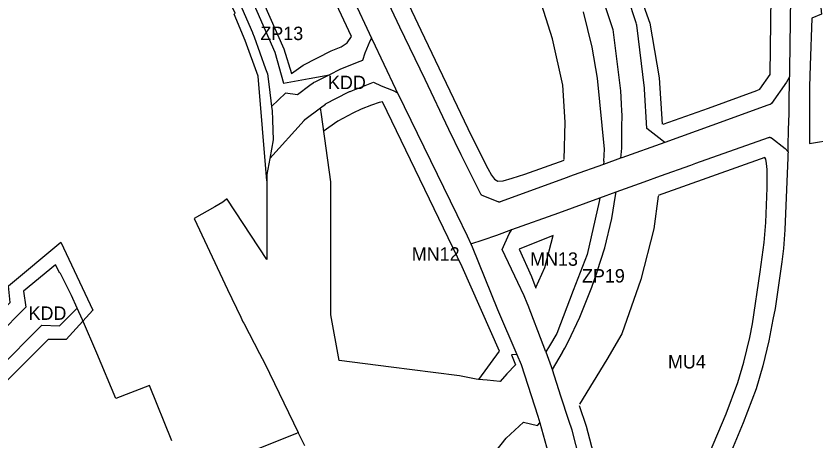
# Model space of a CAD drawing. Extents: x 7428103 to 7431580, y 5545880 to 5549002.
# Drawn here: x 7429886.6 to 7430217.3, y 5547654.9 to 5547830.4 of the extents above; entities that cross this region are included whole.
import ezdxf

# ---------------------------------------------------------------- set-up
doc = ezdxf.new("R2010")
doc.units = 0
for name, color, linetype in [('CZ_L_linie rozgraniczające tereny o różnym przeznaczeniu oraz różnych warunkach ich zabudowy i zagospodarowania', 7, 'Continuous'), ('CZ_L_maksymalne nieprzekraczalne linie zabudowy', 7, 'Continuous'), ('CZ_L_opisy_linie rozgraniczające tereny o różnym przeznaczeniu oraz różnych warunkach ich zabudowy i zagospodarowania', 7, 'Continuous'), ('Łąki_Nowohuckie', 7, 'Continuous')]:
    doc.layers.add(name, color=color, linetype=linetype)

msp = doc.modelspace()

# ---------------------------------------------------------------- linework, layer by layer
at = {"layer": 'CZ_L_linie rozgraniczające tereny o różnym przeznaczeniu oraz różnych warunkach ich zabudowy i zagospodarowania'}
for p, q in [((7430045.43, 5547825.76), (7430030.02, 5547858.79)), ((7430017.37, 5547856.33), (7430033.75, 5547821.24)), ((7429971.54, 5547853.7), (7429984.45, 5547823.58)), ((7429979.57, 5547847.56), (7429993.81, 5547815.38)), ((7430143.29, 5547827.5), (7430136.95, 5547846.57)), ((7430207.23, 5547844.23), (7430206.76, 5547808.41)), ((7430127.52, 5547843.26), (7430133.64, 5547824.82)), ((7430121.33, 5547832.07), (7430124.89, 5547817.41)), ((7430143.39, 5547826.93), (7430143.29, 5547827.5)), ((7430045.44, 5547825.74), (7430045.43, 5547825.76)), ((7430055.96, 5547804.15), (7430045.44, 5547825.74)), ((7430133.64, 5547824.82), (7430136.74, 5547799.38)), ((7430143.51, 5547826.52), (7430143.39, 5547826.93)), ((7430146.68, 5547800.44), (7430143.51, 5547826.52)), ((7429984.45, 5547823.58), (7429984.52, 5547823.42)), ((7429984.52, 5547823.42), (7429985.24, 5547821.72)), ((7429985.24, 5547821.72), (7429989.93, 5547808.56)), ((7430033.75, 5547821.24), (7430032.99, 5547819.91)), ((7430034.12, 5547820.45), (7430033.75, 5547821.24)), ((7430032.99, 5547819.91), (7430031, 5547814.97)), ((7430043.84, 5547800.03), (7430034.12, 5547820.45)), ((7430124.89, 5547817.41), (7430127.16, 5547804.59)), ((7429993.81, 5547815.38), (7429997.37, 5547802.59)), ((7430031, 5547814.97), (7430030, 5547811.9)), ((7430027.84, 5547811.07), (7430020.59, 5547808.23)), ((7430030, 5547811.9), (7430027.84, 5547811.07)), ((7429989.93, 5547808.56), (7429990.71, 5547806.38)), ((7430020.59, 5547808.23), (7430016.36, 5547806.08)), ((7430206.76, 5547808.41), (7430206.74, 5547807.07)), ((7429990.71, 5547806.38), (7429991.36, 5547801.02)), ((7429997.37, 5547802.59), (7430008.01, 5547804.54)), ((7430008.01, 5547804.54), (7430016.36, 5547806.08)), ((7430016.36, 5547806.08), (7430010.53, 5547803.12)), ((7430065.78, 5547783.47), (7430055.96, 5547804.15)), ((7430127.16, 5547804.59), (7430129.96, 5547775.23)), ((7430206.72, 5547805.14), (7430205.44, 5547803.05)), ((7430206.67, 5547801.74), (7430206.72, 5547805.14)), ((7430206.74, 5547807.07), (7430206.72, 5547805.14)), ((7429991.36, 5547801.02), (7429992.37, 5547792.88)), ((7430008.26, 5547801.65), (7430003.16, 5547797.78)), ((7430009.65, 5547802.64), (7430008.26, 5547801.65)), ((7430009.68, 5547802.67), (7430009.65, 5547802.64)), ((7430009.65, 5547802.64), (7430009.65, 5547802.64)), ((7430010.53, 5547803.12), (7430009.68, 5547802.67)), ((7430027.63, 5547800.27), (7430034.64, 5547802.98)), ((7430034.64, 5547802.98), (7430037.8, 5547801.52)), ((7430037.8, 5547801.52), (7430042.71, 5547799.49)), ((7430205.44, 5547803.05), (7430199.23, 5547794.21)), ((7430206.61, 5547797.26), (7430206.67, 5547801.26)), ((7430206.67, 5547801.26), (7430206.67, 5547801.74)), ((7429998.18, 5547798.5), (7429992.37, 5547792.88)), ((7430003.16, 5547797.77), (7429998.18, 5547798.5)), ((7430003.16, 5547797.78), (7430003.16, 5547797.77)), ((7430018.96, 5547796.18), (7430024.67, 5547799.09)), ((7430024.67, 5547799.09), (7430024.76, 5547799.13)), ((7430024.76, 5547799.13), (7430024.89, 5547799.18)), ((7430024.89, 5547799.18), (7430027.61, 5547800.26)), ((7430027.61, 5547800.26), (7430027.63, 5547800.27)), ((7430042.71, 5547799.49), (7430044.51, 5547798.64)), ((7430044.51, 5547798.64), (7430043.84, 5547800.03)), ((7430044.51, 5547798.64), (7430069.01, 5547748.21)), ((7430136.74, 5547799.38), (7430137.07, 5547793.99)), ((7430146.71, 5547800.16), (7430146.68, 5547800.44)), ((7430146.71, 5547800.14), (7430146.71, 5547800.16)), ((7430147.72, 5547783.75), (7430146.71, 5547800.14)), ((7430015.04, 5547794.19), (7430018.96, 5547796.18)), ((7430199.23, 5547794.21), (7430199.18, 5547794.15)), ((7430206.52, 5547790.05), (7430206.6, 5547796.02)), ((7430206.6, 5547796.02), (7430206.61, 5547797.26)), ((7429992.37, 5547792.88), (7429992.58, 5547791.1)), ((7429992.58, 5547791.1), (7429992.73, 5547787.51)), ((7430006.19, 5547787.52), (7430012.59, 5547792.38)), ((7430012.59, 5547792.38), (7430014.66, 5547793.95)), ((7430013.01, 5547789.56), (7430012.59, 5547792.38)), ((7430014.66, 5547793.95), (7430014.7, 5547793.98)), ((7430014.7, 5547793.98), (7430014.83, 5547794.07)), ((7430014.83, 5547794.07), (7430014.97, 5547794.15)), ((7430014.97, 5547794.15), (7430015.04, 5547794.19)), ((7430137.07, 5547793.99), (7430137.26, 5547791)), ((7430137.26, 5547791), (7430137.35, 5547789.46)), ((7430197.69, 5547793.42), (7430174.6, 5547785.04)), ((7430198.63, 5547793.76), (7430197.69, 5547793.42)), ((7430198.66, 5547793.77), (7430198.63, 5547793.76)), ((7430198.73, 5547793.8), (7430198.66, 5547793.77)), ((7430198.8, 5547793.84), (7430198.73, 5547793.8)), ((7430198.88, 5547793.88), (7430198.8, 5547793.84)), ((7430198.94, 5547793.92), (7430198.88, 5547793.88)), ((7430199.01, 5547793.97), (7430198.94, 5547793.92)), ((7430199.03, 5547794), (7430199.01, 5547793.97)), ((7430199.07, 5547794.03), (7430199.03, 5547794)), ((7430199.13, 5547794.09), (7430199.07, 5547794.03)), ((7430199.18, 5547794.15), (7430199.13, 5547794.09)), ((7430016.91, 5547761.69), (7430013.01, 5547789.56)), ((7430137.35, 5547789.46), (7430137.25, 5547784.18)), ((7430206.34, 5547783.33), (7430206.52, 5547790.05)), ((7429992.73, 5547787.51), (7429992.74, 5547787.33)), ((7429992.74, 5547787.33), (7429993.08, 5547779.09)), ((7430002.01, 5547782.9), (7430005.84, 5547787.19)), ((7430005.84, 5547787.19), (7430005.87, 5547787.22)), ((7430005.87, 5547787.22), (7430005.98, 5547787.34)), ((7430005.98, 5547787.34), (7430006.11, 5547787.45)), ((7430006.11, 5547787.45), (7430006.19, 5547787.52)), ((7430174.59, 5547785.04), (7430155.16, 5547778.08)), ((7430174.6, 5547785.04), (7430174.59, 5547785.04)), ((7429995.56, 5547775.68), (7430002.01, 5547782.9)), ((7430065.78, 5547783.46), (7430065.78, 5547783.47)), ((7430070.89, 5547772.95), (7430065.78, 5547783.46)), ((7430137.25, 5547784.18), (7430137.24, 5547777.1)), ((7430153.87, 5547778.95), (7430147.72, 5547783.75)), ((7430206.2, 5547778.05), (7430206.3, 5547781.88)), ((7430206.3, 5547781.88), (7430206.32, 5547782.44)), ((7430206.32, 5547782.44), (7430206.34, 5547783.33)), ((7429993.08, 5547779.09), (7429991.71, 5547771.46)), ((7430155.16, 5547778.08), (7430137.29, 5547771.68)), ((7430154.56, 5547778.49), (7430153.87, 5547778.95)), ((7430155.16, 5547778.08), (7430154.56, 5547778.49)), ((7430167.98, 5547769.42), (7430198.02, 5547780.11)), ((7430198.02, 5547780.11), (7430198.07, 5547780.13)), ((7430198.07, 5547780.13), (7430198.15, 5547780.15)), ((7430198.15, 5547780.15), (7430198.23, 5547780.16)), ((7430198.23, 5547780.16), (7430198.31, 5547780.18)), ((7430198.31, 5547780.18), (7430198.34, 5547780.18)), ((7430198.34, 5547780.18), (7430198.39, 5547780.18)), ((7430198.39, 5547780.18), (7430198.47, 5547780.18)), ((7430198.47, 5547780.18), (7430198.55, 5547780.18)), ((7430198.55, 5547780.18), (7430198.63, 5547780.17)), ((7430198.63, 5547780.17), (7430198.71, 5547780.15)), ((7430198.71, 5547780.15), (7430198.79, 5547780.13)), ((7430198.79, 5547780.13), (7430198.87, 5547780.11)), ((7430198.87, 5547780.11), (7430198.95, 5547780.08)), ((7430198.95, 5547780.08), (7430199.02, 5547780.04)), ((7430199.02, 5547780.04), (7430199.09, 5547780)), ((7430199.09, 5547780), (7430199.16, 5547779.95)), ((7430199.16, 5547779.95), (7430199.2, 5547779.93)), ((7430199.2, 5547779.93), (7430204.88, 5547775.61)), ((7430206.14, 5547775.91), (7430206.2, 5547778.05)), ((7429991.71, 5547771.46), (7429995.56, 5547775.68)), ((7430129.96, 5547775.23), (7430129.79, 5547770.31)), ((7430137.17, 5547775.65), (7430136.87, 5547772.87)), ((7430137.24, 5547777.1), (7430137.17, 5547775.65)), ((7430204.88, 5547775.61), (7430206.1, 5547774.17)), ((7430206.1, 5547774.17), (7430206.14, 5547775.91)), ((7429991.71, 5547771.46), (7429990.5, 5547764.8)), ((7430070.89, 5547772.94), (7430070.89, 5547772.95)), ((7430078.95, 5547756.7), (7430070.89, 5547772.94)), ((7430136.72, 5547771.49), (7430129.75, 5547768.96)), ((7430136.87, 5547772.86), (7430136.72, 5547771.49)), ((7430137.16, 5547771.65), (7430136.72, 5547771.49)), ((7430136.87, 5547772.87), (7430136.87, 5547772.87)), ((7430136.87, 5547772.87), (7430136.87, 5547772.86)), ((7430137.24, 5547771.67), (7430137.16, 5547771.65)), ((7430137.29, 5547771.68), (7430137.24, 5547771.67)), ((7430206.04, 5547771.87), (7430204.83, 5547741.82)), ((7430206.07, 5547773.14), (7430206.04, 5547771.87)), ((7430206.1, 5547774.17), (7430206.07, 5547773.14)), ((7430129.75, 5547768.96), (7430117.24, 5547764.44)), ((7430129.83, 5547770.32), (7430129.75, 5547768.96)), ((7430129.79, 5547770.31), (7430129.83, 5547770.32)), ((7430129.83, 5547770.32), (7430129.83, 5547770.32)), ((7430153.29, 5547764.17), (7430165.88, 5547768.68)), ((7430165.88, 5547768.68), (7430165.89, 5547768.68)), ((7430165.89, 5547768.68), (7430167.98, 5547769.42)), ((7429990.5, 5547764.8), (7429990.45, 5547729.55)), ((7430117.24, 5547764.44), (7430113.24, 5547762.98)), ((7430016.9, 5547706.66), (7430016.91, 5547761.69)), ((7430113.24, 5547762.98), (7430087.05, 5547753.45)), ((7430134.99, 5547757.57), (7430146.63, 5547761.78)), ((7430146.63, 5547761.78), (7430153.29, 5547764.17)), ((7430146.63, 5547761.78), (7430146.63, 5547761.78)), ((7429973.96, 5547754.75), (7429973.07, 5547754)), ((7429974.08, 5547754.57), (7429973.96, 5547754.75)), ((7429990.45, 5547729.55), (7429974.08, 5547754.57)), ((7430078.97, 5547756.66), (7430078.95, 5547756.7)), ((7430079.01, 5547756.59), (7430078.97, 5547756.66)), ((7430079.06, 5547756.52), (7430079.01, 5547756.59)), ((7430079.11, 5547756.46), (7430079.06, 5547756.52)), ((7430079.16, 5547756.4), (7430079.11, 5547756.46)), ((7430079.22, 5547756.34), (7430079.16, 5547756.4)), ((7430079.28, 5547756.29), (7430079.22, 5547756.34)), ((7430079.35, 5547756.24), (7430079.28, 5547756.29)), ((7430079.42, 5547756.19), (7430079.35, 5547756.24)), ((7430079.49, 5547756.15), (7430079.42, 5547756.19)), ((7430079.56, 5547756.12), (7430079.49, 5547756.15)), ((7430079.6, 5547756.1), (7430079.56, 5547756.12)), ((7430086.16, 5547753.46), (7430079.6, 5547756.1)), ((7430111.27, 5547748.98), (7430128.25, 5547755.13)), ((7430128.25, 5547755.13), (7430127.92, 5547753.68)), ((7430128.25, 5547755.13), (7430134.99, 5547757.57)), ((7430133.18, 5547746.64), (7430134.75, 5547756.15)), ((7430134.75, 5547756.15), (7430134.99, 5547757.57)), ((7429968.91, 5547751.38), (7429960.33, 5547746.55)), ((7429972.26, 5547753.32), (7429968.91, 5547751.38)), ((7429973.07, 5547754), (7429972.26, 5547753.32)), ((7430086.19, 5547753.45), (7430086.16, 5547753.46)), ((7430086.27, 5547753.42), (7430086.19, 5547753.45)), ((7430086.35, 5547753.4), (7430086.27, 5547753.42)), ((7430086.43, 5547753.39), (7430086.35, 5547753.4)), ((7430086.51, 5547753.38), (7430086.43, 5547753.39)), ((7430086.59, 5547753.37), (7430086.51, 5547753.38)), ((7430086.67, 5547753.37), (7430086.59, 5547753.37)), ((7430086.76, 5547753.38), (7430086.67, 5547753.37)), ((7430086.84, 5547753.39), (7430086.76, 5547753.38)), ((7430086.92, 5547753.41), (7430086.84, 5547753.39)), ((7430087, 5547753.43), (7430086.92, 5547753.41)), ((7430087.05, 5547753.45), (7430087, 5547753.43)), ((7430127.92, 5547753.68), (7430122.93, 5547731.69)), ((7430069.01, 5547748.21), (7430073.34, 5547739.41)), ((7430091.86, 5547741.96), (7430111.27, 5547748.98)), ((7429960.33, 5547746.55), (7429961.41, 5547744.29)), ((7430130.33, 5547734.43), (7430133.18, 5547746.64)), ((7429961.41, 5547744.29), (7429974.22, 5547717.24)), ((7430085.55, 5547739.68), (7430091.86, 5547741.96)), ((7430090.68, 5547740.2), (7430091.86, 5547741.96)), ((7430204.83, 5547741.82), (7430204.28, 5547734.11)), ((7430073.34, 5547739.41), (7430073.36, 5547739.38)), ((7430073.36, 5547739.38), (7430074.89, 5547736.05)), ((7430079.96, 5547737.77), (7430085.55, 5547739.68)), ((7430087.8, 5547733.75), (7430090.68, 5547740.2)), ((7430074.89, 5547736.05), (7430079.96, 5547737.77)), ((7430074.89, 5547736.05), (7430075.36, 5547734.89)), ((7430075.36, 5547734.89), (7430085.84, 5547708.89)), ((7430094.27, 5547720.15), (7430087.8, 5547733.75)), ((7430122.92, 5547731.66), (7430117.21, 5547716.8)), ((7430122.93, 5547731.69), (7430122.92, 5547731.66)), ((7430127.09, 5547724.61), (7430130.33, 5547734.43)), ((7430204.28, 5547734.11), (7430203.5, 5547728.68)), ((7430203.5, 5547728.68), (7430200.71, 5547709.32)), ((7429903.01, 5547727.36), (7429889.81, 5547716.57)), ((7429904.82, 5547724.02), (7429903.01, 5547727.36)), ((7429904.88, 5547724.08), (7429904.82, 5547724.02)), ((7429904.94, 5547724.14), (7429904.88, 5547724.08)), ((7429909.68, 5547714.73), (7429904.94, 5547724.14)), ((7430124.92, 5547718.13), (7430127.07, 5547724.55)), ((7430127.07, 5547724.55), (7430127.18, 5547724.62)), ((7430127.18, 5547724.62), (7430127.09, 5547724.61)), ((7430096.94, 5547714.53), (7430094.27, 5547720.15)), ((7429889.81, 5547716.57), (7429890.68, 5547709.85)), ((7429974.22, 5547717.24), (7429979.63, 5547705.8)), ((7430117.21, 5547716.8), (7430110.49, 5547699.06)), ((7430120, 5547705.75), (7430124.92, 5547718.13)), ((7429911.96, 5547709.54), (7429909.68, 5547714.73)), ((7430098.14, 5547711.61), (7430096.94, 5547714.53)), ((7430098.56, 5547710.53), (7430098.14, 5547711.61)), ((7429890.68, 5547709.85), (7429839.69, 5547658.72)), ((7429904.66, 5547702.16), (7429911.53, 5547709.12)), ((7429911.53, 5547709.12), (7429911.96, 5547709.54)), ((7429914.14, 5547704.58), (7429911.96, 5547709.54)), ((7430085.84, 5547708.89), (7430093.88, 5547690.36)), ((7430104.84, 5547694.26), (7430098.56, 5547710.53)), ((7430200.71, 5547709.32), (7430199.84, 5547704.8)), ((7429979.63, 5547705.8), (7429980.57, 5547703.88)), ((7430020.41, 5547687.86), (7430016.9, 5547706.66)), ((7430115.13, 5547695.6), (7430120, 5547705.75)), ((7429848.02, 5547652.92), (7429897.36, 5547702.38)), ((7429897.36, 5547702.38), (7429904.66, 5547702.16)), ((7429920.16, 5547690.79), (7429914.14, 5547704.58)), ((7429980.57, 5547703.88), (7429980.87, 5547703.31)), ((7429980.87, 5547703.31), (7429987.46, 5547690.71)), ((7430199.84, 5547704.8), (7430198.13, 5547695.91)), ((7430110.49, 5547699.06), (7430107.38, 5547693.86)), ((7430113.79, 5547692.98), (7430115.13, 5547695.6)), ((7430198.13, 5547695.91), (7430195.74, 5547685.63)), ((7430105.87, 5547691.41), (7430104.84, 5547694.26)), ((7430107.38, 5547693.86), (7430105.87, 5547691.41)), ((7430112.78, 5547691.22), (7430113.79, 5547692.98)), ((7429928, 5547672.1), (7429920.16, 5547690.79)), ((7429987.46, 5547690.71), (7429989.59, 5547686.64)), ((7430093.88, 5547690.36), (7430091.62, 5547690.16)), ((7430091.62, 5547690.16), (7430093.33, 5547685.98)), ((7430093.88, 5547690.36), (7430095.69, 5547686.19)), ((7430105.87, 5547691.41), (7430108.63, 5547683.8)), ((7430108.7, 5547684.15), (7430112.75, 5547691.18)), ((7430112.75, 5547691.18), (7430112.78, 5547691.22)), ((7429989.59, 5547686.64), (7430003.44, 5547658)), ((7430041.87, 5547685.11), (7430020.41, 5547687.86)), ((7430059.26, 5547682.88), (7430041.87, 5547685.11)), ((7430093.33, 5547685.98), (7430089.79, 5547682.33)), ((7430095.69, 5547686.19), (7430102.56, 5547664.82)), ((7430195.74, 5547685.63), (7430192.86, 5547676.11)), ((7430070.19, 5547681.48), (7430059.26, 5547682.88)), ((7430089.79, 5547682.33), (7430086.93, 5547679.19)), ((7430108.63, 5547683.8), (7430108.67, 5547683.97)), ((7430108.67, 5547683.97), (7430108.7, 5547684.15)), ((7430112.07, 5547673.1), (7430108.67, 5547683.97)), ((7430077.03, 5547680.08), (7430070.19, 5547681.48)), ((7430077.98, 5547679.98), (7430077.03, 5547680.08)), ((7430081.55, 5547679.63), (7430077.98, 5547679.98)), ((7430086.89, 5547679.14), (7430081.55, 5547679.63)), ((7430086.93, 5547679.19), (7430086.89, 5547679.14)), ((7429941.9, 5547677.46), (7429928, 5547672.1)), ((7429951.07, 5547654.57), (7429941.9, 5547677.46)), ((7430192.86, 5547676.11), (7430187.6, 5547662.03)), ((7430115.42, 5547663.03), (7430112.07, 5547673.1)), ((7430089.49, 5547655.67), (7430096.6, 5547662.31)), ((7430096.6, 5547662.31), (7430102.42, 5547660.87)), ((7430102.49, 5547660.96), (7430103.34, 5547662.02)), ((7430102.56, 5547664.82), (7430103.34, 5547662.02)), ((7430103.34, 5547662.02), (7430109.29, 5547640.69)), ((7430116.77, 5547658.97), (7430115.42, 5547663.03)), ((7430187.6, 5547662.03), (7430175.91, 5547634.4)), ((7430102.42, 5547660.87), (7430102.49, 5547660.96)), ((7430121.68, 5547640.08), (7430116.77, 5547658.97)), ((7430002.31, 5547657.48), (7429957.13, 5547639.45)), ((7430002.39, 5547657.51), (7430002.31, 5547657.48)), ((7430003.44, 5547658), (7430002.39, 5547657.51)), ((7430003.44, 5547658), (7430003.46, 5547657.95)), ((7430003.46, 5547657.95), (7430006.08, 5547652.64)), ((7430080.55, 5547644.47), (7430089.49, 5547655.67))]:
    msp.add_line(p, q, dxfattribs=at)
at = {"layer": 'CZ_L_maksymalne nieprzekraczalne linie zabudowy'}
for points in [[(7430154.46, 5547785.67), (7430173.26, 5547792.27), (7430193.23, 5547799.51), (7430194.45, 5547800.07), (7430198.73, 5547806.16), (7430199.09, 5547838.74), (7430198.96, 5547850.56), (7430197.64, 5547869.4), (7430193.56, 5547919.92), (7430185.06, 5548067.1)], [(7430038.72, 5548043.09), (7430077.31, 5547970.06), (7430086.5, 5547953.36), (7430128.11, 5547878.81), (7430130.86, 5547873.57), (7430137.78, 5547858.77), (7430148.85, 5547827.42), (7430152.72, 5547804.73), (7430154.06, 5547785.65)], [(7430048.28, 5547939.26), (7430006.56, 5547915.24), (7430007.43, 5547914.05), (7430032.87, 5547869.41), (7430036.42, 5547862.2), (7430054.13, 5547824.56), (7430075.19, 5547780.71), (7430081.91, 5547767.24), (7430083.41, 5547764.56), (7430084.64, 5547762.79), (7430086.05, 5547762.01), (7430088.28, 5547762.16), (7430091.98, 5547763.2), (7430097.25, 5547764.96), (7430113.46, 5547770.78)], [(7430113.47, 5547770.96), (7430113.92, 5547786.47), (7430112.97, 5547801.79), (7430108.6, 5547820.89), (7430103.33, 5547837.99), (7430099.01, 5547847.95), (7430085.78, 5547872.45), (7430069.26, 5547902.4), (7430048.34, 5547939.16)], [(7429980.24, 5547856.67), (7429980.15, 5547856.9), (7429983.26, 5547849.11), (7429997.54, 5547816.81), (7430000.65, 5547806.54), (7430005.49, 5547810.06), (7430017.01, 5547815.94), (7430021.16, 5547817.67), (7430023.62, 5547819.29), (7430025.47, 5547821.84), (7430010.85, 5547853.18), (7430008.65, 5547858.85), (7430007.4, 5547859.89), (7430006.5, 5547861.03), (7429988.64, 5547892.24), (7429967.56, 5547927.89), (7429949.13, 5547908.5)], [(7429990.5, 5547762.22), (7429986.79, 5547805.45), (7429981.51, 5547820.27), (7429976.89, 5547831.08), (7429977.35, 5547831.48), (7429972.08, 5547842.28), (7429967.92, 5547852), (7429957.38, 5547872.53), (7429959.82, 5547873.88), (7429944.75, 5547897.93), (7429942.41, 5547896.31), (7429940.29, 5547899)], [(7430078.14, 5547679.97), (7430086.72, 5547691.67), (7430071.29, 5547726.56), (7430038.31, 5547794.83), (7430036.96, 5547794.62), (7430033.8, 5547793.53), (7430029.52, 5547791.85), (7430025.96, 5547790.17), (7430019.87, 5547786.8), (7430013.81, 5547782.63)], [(7430119.71, 5547669.15), (7430122.51, 5547660.71), (7430131.89, 5547624.92), (7430132.14, 5547620.6), (7430132.97, 5547616.57), (7430135.86, 5547608.04), (7430142.03, 5547583.6), (7430142.27, 5547583.04), (7430143.24, 5547582.19), (7430161.35, 5547620.52), (7430180.46, 5547665.78), (7430185.28, 5547678.67), (7430187.86, 5547687.18), (7430190.24, 5547697.29), (7430191.35, 5547703.01), (7430194.6, 5547724.45), (7430196.19, 5547736.58), (7430196.87, 5547744.92), (7430197.42, 5547759.23), (7430197.41, 5547766.79), (7430197.23, 5547769.37), (7430196.92, 5547771.13), (7430196.44, 5547771.85), (7430152.39, 5547756.12)], [(7430152.35, 5547755.81), (7430150.62, 5547742.3), (7430145.19, 5547721.39), (7430137.4, 5547698.87), (7430131.17, 5547688.19), (7430119.82, 5547669.78)], [(7430108.85, 5547739.53), (7430094.86, 5547733.89), (7430099.98, 5547722.52), (7430101.73, 5547717.78)], [(7430101.7, 5547718.07), (7430105.44, 5547726.33), (7430108.85, 5547739.53)], [(7429834.21, 5547661.77), (7429884.22, 5547711.87), (7429883.54, 5547718.65), (7429905.23, 5547736.82), (7429918.38, 5547708.67), (7429907.44, 5547696.52), (7429900, 5547696.54), (7429850.84, 5547647.53)]]:
    msp.add_lwpolyline(points, dxfattribs=at)
at = {"layer": 'Łąki_Nowohuckie'}
for p, q in [((7430215.02, 5547801.16), (7430214.96, 5547783.63)), ((7430214.96, 5547783.63), (7430214.92, 5547777.68)), ((7430214.92, 5547777.68), (7430235.46, 5547780.82))]:
    msp.add_line(p, q, dxfattribs=at)
for points in [[(7430215.11, 5547877.13), (7430216.71, 5547862.02), (7430219.99, 5547831.09), (7430215.97, 5547829.51)], [(7430215.97, 5547829.51), (7430215.3, 5547809.94), (7430215.02, 5547801.16)]]:
    msp.add_lwpolyline(points, dxfattribs=at)

# ---------------------------------------------------------------- texts
at = {"layer": 'CZ_L_opisy_linie rozgraniczające tereny o różnym przeznaczeniu oraz różnych warunkach ich zabudowy i zagospodarowania'}
for s, p in [('ZP13', (7429987.75, 5547820.41)), ('KDD', (7430015.73, 5547800.11)), ('MN12', (7430050.42, 5547729.12)), ('MN13', (7430099.38, 5547727.01)), ('ZP19', (7430120.83, 5547720.09)), ('KDD', (7429891.83, 5547704.64)), ('MU4', (7430156.41, 5547684.52))]:
    msp.add_text(s, height=5.549, dxfattribs=at).set_placement(p)

doc.saveas('drawing.dxf')
